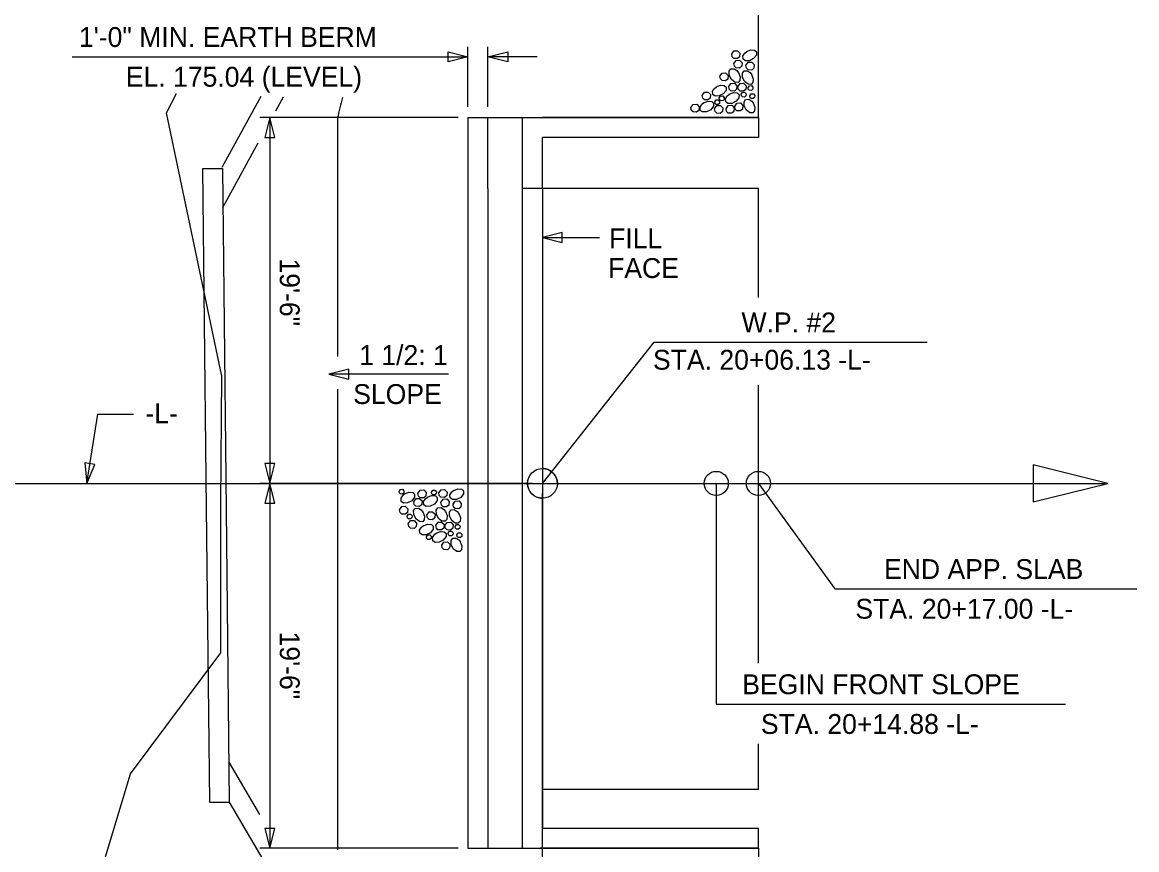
# Model space of a CAD drawing. Extents: x 471 to 2034, y -623 to 126.
# Drawn here: x 1602 to 1658.1, y -51.7 to -10 of the extents above; entities that cross this region are included whole.
import ezdxf

# ---------------------------------------------------------------- set-up
doc = ezdxf.new("R2010")
doc.units = 0
for name, color, linetype in [('Arrowhead Terminators CELL', 7, 'Continuous'), ('Auto Dimensioning', 7, 'Continuous'), ('Default', 7, 'Continuous'), ('Dimension Lines', 7, 'Continuous'), ('Exist Hydro Stream or Body of Water', 7, 'Continuous'), ('Exist Structure Major Bridge Seam', 7, 'Continuous'), ('Mis -L- Lines', 7, 'Continuous'), ('Mis Object Lines', 7, 'Continuous'), ('Mis Object Lines Hidden', 7, 'Continuous'), ('Mis Work Point CELL', 7, 'Continuous'), ('Miscellaneous Lines CELL', 7, 'Continuous'), ('Sub End Bent Cap Lines CELL', 7, 'Continuous'), ('Sup Concrete Girder Lines', 7, 'Continuous'), ('Text', 7, 'Continuous'), ('User Information Notes', 7, 'Continuous')]:
    doc.layers.add(name, color=color, linetype=linetype)

# ---------------------------------------------------------------- blocks, each defined once
blk = doc.blocks.new('AH')
at = {"layer": 'Sub End Bent Cap Lines CELL'}
blk.add_lwpolyline([(0, 0), (-1.25, 0.312), (-1.25, -0.312)], close=True, dxfattribs=at)

msp = doc.modelspace()

# ---------------------------------------------------------------- linework, layer by layer
at = {"layer": 'Arrowhead Terminators CELL'}
for points in [[(1628.207, -20.833), (1629.207, -21.083), (1629.207, -20.583)], [(1617.459, -27.719), (1618.459, -27.969), (1618.459, -27.469)], [(1605.264, -33.216), (1605.67, -32.268), (1605.176, -32.189)], [(1656.665, -33.216), (1652.915, -32.279), (1652.915, -34.154)]]:
    msp.add_lwpolyline(points, close=True, dxfattribs=at)
at = {"layer": 'Auto Dimensioning'}
for p, q in [((1623.957, -14.799), (1613.986, -14.799)), ((1614.486, -14.799), (1614.486, -33.216)), ((1627.707, -33.216), (1613.986, -33.216)), ((1614.486, -33.216), (1614.486, -51.588)), ((1628.189, -33.716), (1628.189, -65.55)), ((1623.957, -51.588), (1613.986, -51.588))]:
    msp.add_line(p, q, dxfattribs=at)
at = {"layer": 'Default'}
msp.add_line((1628.097, -51.588), (1638.097, -51.588), dxfattribs=at)
at = {"layer": 'Dimension Lines'}
for p, q in [((1604.538, -11.74), (1624.457, -11.74)), ((1624.457, -14.26), (1624.457, -11.24)), ((1625.457, -14.26), (1625.457, -11.24)), ((1627.938, -11.74), (1625.457, -11.74)), ((1628.207, -20.833), (1631.085, -20.833)), ((1628.207, -33.216), (1633.837, -26.111)), ((1633.837, -26.111), (1647.57, -26.111)), ((1623.481, -27.719), (1617.459, -27.719)), ((1605.264, -33.216), (1605.824, -29.735)), ((1605.824, -29.735), (1607.626, -29.735)), ((1636.957, -33.216), (1636.957, -44.333)), ((1639.077, -33.216), (1642.921, -38.531)), ((1642.921, -38.531), (1658.123, -38.531)), ((1636.957, -44.333), (1654.53, -44.333))]:
    msp.add_line(p, q, dxfattribs=at)
for centre in [(1636.957, -33.216), (1639.077, -33.216)]:
    msp.add_circle(centre, 0.606, dxfattribs=at)
at = {"layer": 'Exist Hydro Stream or Body of Water'}
for points in [[(1609.289, -14.552), (1609.784, -13.589)], [(1607.464, -47.845), (1612.022, -41.753), (1612.015, -34.19), (1612.069, -27.811), (1609.289, -14.552)], [(1607.95, -58.766), (1606.211, -52.027), (1607.464, -47.845)]]:
    msp.add_lwpolyline(points, dxfattribs=at)
at = {"layer": 'Exist Structure Major Bridge Seam'}
for p, q in [((1612.085, -17.293), (1614.049, -13.712)), ((1614.782, -14.457), (1615.172, -13.745)), ((1612.114, -19.32), (1613.899, -16.067)), ((1611.093, -17.359), (1612.093, -17.359)), ((1612.413, -47.257), (1613.959, -49.887)), ((1611.441, -49.277), (1612.441, -49.277)), ((1612.441, -49.277), (1617.662, -58.16))]:
    msp.add_line(p, q, dxfattribs=at)
for points in [[(1611.093, -17.359), (1611.263, -32.933), (1611.441, -49.277)], [(1612.093, -17.359), (1612.263, -32.933), (1612.441, -49.277)]]:
    msp.add_lwpolyline(points, dxfattribs=at)
at = {"layer": 'Mis -L- Lines'}
msp.add_line((1529.284, -33.216), (1656.541, -33.216), dxfattribs=at)
at = {"layer": 'Mis Object Lines'}
for p, q in [((1624.457, -14.799), (1639.077, -14.799)), ((1624.457, -14.799), (1624.457, -51.588)), ((1625.457, -18.362), (1625.457, -14.799)), ((1627.207, -51.588), (1627.207, -14.799)), ((1639.077, -14.799), (1639.077, -15.799)), ((1639.077, -15.799), (1628.207, -15.799)), ((1628.207, -18.362), (1628.207, -15.799)), ((1625.457, -18.362), (1625.457, -51.588)), ((1639.077, -18.362), (1627.207, -18.362)), ((1639.077, -23.863), (1639.077, -18.362)), ((1639.077, -42.275), (1639.077, -28.274)), ((1639.077, -48.633), (1639.077, -46.33)), ((1639.077, -48.633), (1628.207, -48.633)), ((1628.207, -48.633), (1628.207, -50.588)), ((1639.077, -50.588), (1628.207, -50.588)), ((1639.077, -51.588), (1639.077, -50.588)), ((1624.457, -51.588), (1639.077, -51.588))]:
    msp.add_line(p, q, dxfattribs=at)
at = {"layer": 'Mis Object Lines Hidden'}
msp.add_line((1628.207, -18.362), (1628.207, -49.196), dxfattribs=at)
at = {"layer": 'Mis Work Point CELL'}
for p, q in [((1628.207, -32.466), (1628.207, -33.216)), ((1627.457, -33.216), (1628.207, -33.216)), ((1628.207, -33.216), (1628.207, -33.966)), ((1628.207, -33.216), (1628.957, -33.216)), ((1628.957, -33.216), (1628.957, -33.216)), ((1628.207, -33.966), (1628.207, -33.966))]:
    msp.add_line(p, q, dxfattribs=at)
msp.add_circle((1628.207, -33.216), 0.75, dxfattribs=at)
for start, end in [(359.997, 89.9989), (180.0011, 270.003)]:
    msp.add_arc((1628.207, -33.216), 0.75, start, end, dxfattribs=at)
at = {"layer": 'Miscellaneous Lines CELL'}
for points in [[(1637.735, -11.596), (1637.847, -11.437), (1638.026, -11.427), (1638.15, -11.556), (1638.132, -11.736), (1638.022, -11.828), (1637.845, -11.816), (1637.762, -11.735), (1637.735, -11.596)], [(1638.487, -11.469), (1638.696, -11.386), (1638.889, -11.403), (1638.981, -11.49), (1638.978, -11.646), (1638.839, -11.823), (1638.624, -11.931), (1638.422, -11.934), (1638.308, -11.853), (1638.297, -11.692), (1638.39, -11.548), (1638.495, -11.464)], [(1638.074, -12.528), (1638.157, -12.737), (1638.14, -12.93), (1638.053, -13.021), (1637.897, -13.018), (1637.719, -12.88), (1637.612, -12.665), (1637.608, -12.463), (1637.689, -12.349), (1637.85, -12.338), (1637.995, -12.43), (1638.079, -12.536)], [(1637.84, -12.074), (1637.952, -11.914), (1638.131, -11.904), (1638.256, -12.033), (1638.238, -12.214), (1638.127, -12.306), (1637.951, -12.293), (1637.867, -12.212), (1637.841, -12.074)], [(1638.453, -12.171), (1638.565, -12.012), (1638.744, -12.002), (1638.868, -12.131), (1638.85, -12.311), (1638.74, -12.403), (1638.563, -12.39), (1638.48, -12.31), (1638.453, -12.171)], [(1637.136, -12.713), (1637.248, -12.554), (1637.427, -12.544), (1637.551, -12.673), (1637.533, -12.853), (1637.423, -12.945), (1637.246, -12.933), (1637.163, -12.852), (1637.136, -12.713)], [(1638.738, -12.629), (1638.821, -12.839), (1638.804, -13.031), (1638.717, -13.123), (1638.561, -13.12), (1638.384, -12.981), (1638.276, -12.767), (1638.273, -12.564), (1638.354, -12.45), (1638.515, -12.44), (1638.659, -12.532), (1638.743, -12.638)], [(1636.959, -13.248), (1637.169, -13.164), (1637.362, -13.181), (1637.453, -13.268), (1637.45, -13.424), (1637.311, -13.602), (1637.097, -13.709), (1636.894, -13.713), (1636.781, -13.632), (1636.77, -13.471), (1636.862, -13.327), (1636.968, -13.242)], [(1637.584, -13.233), (1637.697, -13.074), (1637.875, -13.063), (1638, -13.192), (1637.982, -13.373), (1637.871, -13.465), (1637.695, -13.452), (1637.612, -13.372), (1637.585, -13.233)], [(1638.045, -13.24), (1638.157, -13.08), (1638.336, -13.07), (1638.461, -13.199), (1638.443, -13.38), (1638.332, -13.472), (1638.156, -13.459), (1638.072, -13.378), (1638.046, -13.24)], [(1638.555, -13.289), (1638.622, -13.193), (1638.73, -13.187), (1638.804, -13.265), (1638.794, -13.373), (1638.727, -13.428), (1638.621, -13.42), (1638.571, -13.372), (1638.555, -13.289)], [(1636.329, -14.049), (1636.538, -13.966), (1636.731, -13.982), (1636.823, -14.07), (1636.82, -14.226), (1636.681, -14.403), (1636.466, -14.511), (1636.264, -14.514), (1636.15, -14.433), (1636.139, -14.272), (1636.231, -14.128), (1636.337, -14.044)], [(1636.251, -13.678), (1636.363, -13.519), (1636.541, -13.509), (1636.666, -13.638), (1636.648, -13.818), (1636.537, -13.91), (1636.361, -13.898), (1636.278, -13.817), (1636.251, -13.678)], [(1636.879, -14.004), (1636.946, -13.908), (1637.054, -13.902), (1637.128, -13.979), (1637.118, -14.088), (1637.051, -14.143), (1636.945, -14.135), (1636.895, -14.087), (1636.879, -14.004)], [(1637.11, -13.809), (1637.178, -13.713), (1637.285, -13.707), (1637.36, -13.785), (1637.349, -13.893), (1637.282, -13.948), (1637.176, -13.941), (1637.127, -13.892), (1637.11, -13.809)], [(1637.61, -13.622), (1637.819, -13.539), (1638.012, -13.556), (1638.103, -13.643), (1638.101, -13.799), (1637.962, -13.976), (1637.747, -14.084), (1637.545, -14.087), (1637.431, -14.006), (1637.42, -13.845), (1637.512, -13.701), (1637.618, -13.617)], [(1638.208, -13.625), (1638.276, -13.53), (1638.383, -13.523), (1638.458, -13.601), (1638.447, -13.709), (1638.381, -13.764), (1638.275, -13.757), (1638.225, -13.708), (1638.209, -13.625)], [(1638.819, -14.06), (1638.902, -14.269), (1638.886, -14.462), (1638.799, -14.553), (1638.642, -14.55), (1638.465, -14.411), (1638.357, -14.197), (1638.354, -13.995), (1638.435, -13.881), (1638.596, -13.87), (1638.74, -13.962), (1638.825, -14.068)], [(1638.65, -13.704), (1638.717, -13.608), (1638.824, -13.602), (1638.899, -13.68), (1638.888, -13.788), (1638.822, -13.843), (1638.716, -13.836), (1638.666, -13.787), (1638.65, -13.704)], [(1635.683, -14.295), (1635.795, -14.135), (1635.974, -14.125), (1636.098, -14.254), (1636.08, -14.435), (1635.969, -14.527), (1635.793, -14.514), (1635.71, -14.433), (1635.683, -14.295)], [(1636.872, -14.354), (1636.984, -14.194), (1637.163, -14.184), (1637.287, -14.313), (1637.269, -14.494), (1637.158, -14.586), (1636.982, -14.573), (1636.899, -14.492), (1636.872, -14.354)], [(1637.45, -14.347), (1637.562, -14.188), (1637.741, -14.178), (1637.865, -14.307), (1637.847, -14.487), (1637.737, -14.579), (1637.56, -14.566), (1637.477, -14.486), (1637.45, -14.347)], [(1637.884, -14.23), (1637.996, -14.071), (1638.175, -14.061), (1638.3, -14.19), (1638.282, -14.37), (1638.171, -14.462), (1637.994, -14.449), (1637.911, -14.369), (1637.884, -14.23)], [(1620.987, -33.617), (1621.054, -33.521), (1621.162, -33.515), (1621.236, -33.592), (1621.225, -33.701), (1621.159, -33.756), (1621.053, -33.748), (1621.003, -33.7), (1620.987, -33.617)], [(1621.277, -33.74), (1621.487, -33.656), (1621.68, -33.673), (1621.771, -33.76), (1621.768, -33.916), (1621.629, -34.094), (1621.415, -34.201), (1621.212, -34.205), (1621.098, -34.124), (1621.088, -33.963), (1621.18, -33.819), (1621.286, -33.734)], [(1621.941, -33.719), (1622.053, -33.56), (1622.232, -33.549), (1622.357, -33.678), (1622.339, -33.859), (1622.228, -33.951), (1622.051, -33.938), (1621.968, -33.858), (1621.941, -33.719)], [(1622.621, -33.654), (1622.688, -33.558), (1622.796, -33.552), (1622.87, -33.629), (1622.859, -33.738), (1622.793, -33.793), (1622.687, -33.785), (1622.637, -33.737), (1622.621, -33.654)], [(1622.988, -33.695), (1623.1, -33.536), (1623.279, -33.525), (1623.404, -33.654), (1623.386, -33.835), (1623.275, -33.927), (1623.098, -33.914), (1623.015, -33.833), (1622.988, -33.695)], [(1623.74, -33.567), (1623.95, -33.484), (1624.142, -33.501), (1624.234, -33.588), (1624.231, -33.744), (1624.092, -33.922), (1623.877, -34.029), (1623.675, -34.033), (1623.561, -33.952), (1623.55, -33.791), (1623.643, -33.646), (1623.749, -33.562)], [(1621.73, -34.141), (1621.842, -33.981), (1622.021, -33.971), (1622.146, -34.1), (1622.128, -34.281), (1622.017, -34.373), (1621.841, -34.36), (1621.757, -34.279), (1621.73, -34.141)], [(1622.416, -33.909), (1622.626, -33.826), (1622.818, -33.843), (1622.91, -33.93), (1622.907, -34.086), (1622.768, -34.263), (1622.553, -34.371), (1622.351, -34.374), (1622.237, -34.293), (1622.226, -34.132), (1622.319, -33.988), (1622.425, -33.904)], [(1623.094, -34.172), (1623.206, -34.013), (1623.385, -34.002), (1623.509, -34.131), (1623.491, -34.312), (1623.38, -34.404), (1623.204, -34.391), (1623.121, -34.311), (1623.094, -34.172)], [(1623.706, -34.27), (1623.818, -34.11), (1623.997, -34.1), (1624.122, -34.229), (1624.104, -34.41), (1623.993, -34.502), (1623.816, -34.489), (1623.733, -34.408), (1623.706, -34.27)], [(1621.012, -34.541), (1621.124, -34.381), (1621.303, -34.371), (1621.427, -34.5), (1621.409, -34.681), (1621.299, -34.773), (1621.122, -34.76), (1621.039, -34.679), (1621.012, -34.541)], [(1621.397, -34.867), (1621.464, -34.772), (1621.571, -34.766), (1621.646, -34.843), (1621.635, -34.951), (1621.569, -35.006), (1621.463, -34.999), (1621.413, -34.95), (1621.397, -34.867)], [(1622.188, -34.653), (1622.271, -34.863), (1622.255, -35.055), (1622.168, -35.147), (1622.011, -35.144), (1621.834, -35.005), (1621.726, -34.79), (1621.723, -34.588), (1621.804, -34.474), (1621.965, -34.464), (1622.109, -34.556), (1622.193, -34.662)], [(1622.389, -34.812), (1622.501, -34.652), (1622.68, -34.642), (1622.805, -34.771), (1622.787, -34.952), (1622.676, -35.044), (1622.5, -35.031), (1622.416, -34.95), (1622.389, -34.812)], [(1623.327, -34.626), (1623.41, -34.836), (1623.393, -35.028), (1623.306, -35.12), (1623.15, -35.117), (1622.973, -34.978), (1622.865, -34.763), (1622.862, -34.561), (1622.943, -34.447), (1623.104, -34.436), (1623.248, -34.529), (1623.332, -34.635)], [(1623.991, -34.728), (1624.074, -34.937), (1624.058, -35.13), (1623.971, -35.221), (1623.814, -35.219), (1623.637, -35.08), (1623.53, -34.865), (1623.526, -34.663), (1623.607, -34.549), (1623.768, -34.538), (1623.912, -34.63), (1623.997, -34.736)], [(1621.454, -35.252), (1621.566, -35.093), (1621.745, -35.083), (1621.869, -35.212), (1621.851, -35.392), (1621.741, -35.484), (1621.564, -35.472), (1621.481, -35.391), (1621.454, -35.252)], [(1622.213, -35.346), (1622.422, -35.263), (1622.615, -35.28), (1622.706, -35.367), (1622.704, -35.523), (1622.565, -35.7), (1622.35, -35.808), (1622.148, -35.811), (1622.034, -35.73), (1622.023, -35.569), (1622.115, -35.425), (1622.221, -35.341)], [(1622.838, -35.331), (1622.95, -35.172), (1623.129, -35.162), (1623.253, -35.291), (1623.235, -35.471), (1623.125, -35.563), (1622.948, -35.551), (1622.865, -35.47), (1622.838, -35.331)], [(1623.299, -35.338), (1623.411, -35.179), (1623.59, -35.169), (1623.714, -35.298), (1623.696, -35.478), (1623.586, -35.57), (1623.409, -35.557), (1623.326, -35.477), (1623.299, -35.338)], [(1623.809, -35.387), (1623.876, -35.292), (1623.983, -35.286), (1624.058, -35.363), (1624.047, -35.471), (1623.981, -35.527), (1623.875, -35.519), (1623.825, -35.471), (1623.809, -35.387)], [(1622.364, -35.908), (1622.431, -35.812), (1622.538, -35.806), (1622.613, -35.883), (1622.602, -35.992), (1622.536, -36.047), (1622.43, -36.039), (1622.38, -35.991), (1622.364, -35.908)], [(1622.863, -35.72), (1623.073, -35.637), (1623.265, -35.654), (1623.357, -35.741), (1623.354, -35.897), (1623.215, -36.075), (1623, -36.182), (1622.798, -36.186), (1622.684, -36.105), (1622.673, -35.944), (1622.766, -35.799), (1622.872, -35.715)], [(1623.462, -35.724), (1623.529, -35.628), (1623.636, -35.622), (1623.711, -35.699), (1623.7, -35.808), (1623.634, -35.863), (1623.528, -35.855), (1623.478, -35.807), (1623.462, -35.724)], [(1623.903, -35.802), (1623.97, -35.707), (1624.078, -35.701), (1624.152, -35.778), (1624.141, -35.886), (1624.075, -35.942), (1623.969, -35.934), (1623.919, -35.886), (1623.903, -35.803)], [(1623.138, -36.329), (1623.25, -36.169), (1623.429, -36.159), (1623.553, -36.288), (1623.535, -36.469), (1623.424, -36.561), (1623.248, -36.548), (1623.165, -36.467), (1623.138, -36.329)], [(1624.072, -36.158), (1624.156, -36.368), (1624.139, -36.56), (1624.052, -36.652), (1623.896, -36.649), (1623.718, -36.51), (1623.611, -36.295), (1623.607, -36.093), (1623.688, -35.979), (1623.849, -35.968), (1623.993, -36.061), (1624.078, -36.167)]]:
    msp.add_lwpolyline(points, dxfattribs=at)
at = {"layer": 'Sup Concrete Girder Lines'}
for p, q in [((1639.077, -14.824), (1639.077, 1.002)), ((1617.889, -14.831), (1617.889, -26.825)), ((1639.077, -14.799), (1628.207, -14.799)), ((1617.889, -28.475), (1617.889, -51.664)), ((1639.097, -51.588), (1628.097, -51.588)), ((1639.077, -51.588), (1639.077, -72.216))]:
    msp.add_line(p, q, dxfattribs=at)
msp.add_arc((1637.282, -18.801), 19.795, 165.3232, 168.4317, dxfattribs=at)
at = {"layer": 'User Information Notes'}
msp.add_line((1628.207, -33.216), (1628.207, -33.216), dxfattribs=at)
msp.add_line((1628.207, -33.216), (1628.207, -33.216), dxfattribs=at)

# ---------------------------------------------------------------- block references
at = {"layer": 'Arrowhead Terminators CELL', "xscale": 0.8, "yscale": -0.8000000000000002}
msp.add_blockref('AH', (1624.457, -11.74), dxfattribs=at)
at = {"layer": 'Arrowhead Terminators CELL', "xscale": 0.8, "yscale": -0.8000000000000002, "rotation": 180}
msp.add_blockref('AH', (1625.457, -11.74), dxfattribs=at)
at = {"layer": 'Auto Dimensioning', "xscale": 0.8, "yscale": 0.8000000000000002}
for p, rotation in [((1614.486, -14.799), 90), ((1614.486, -33.216), -90), ((1614.486, -33.216), 90), ((1614.486, -51.588), -90)]:
    msp.add_blockref('AH', p, dxfattribs=dict(at, rotation=rotation))

# ---------------------------------------------------------------- texts
at = {"layer": 'Dimension Lines'}
for s, p in [('FILL', (1631.561, -21.374)), ('FACE', (1631.51, -22.874)), ('-L-', (1608.22, -30.188))]:
    msp.add_text(s, height=1, dxfattribs=at).set_placement(p)
at = {"layer": 'Text'}
for s, p in [('1\'-0" MIN. EARTH BERM', (1604.873, -11.24)), ('EL. 175.04 (LEVEL)', (1607.232, -13.24)), ('W.P. #2', (1638.227, -25.611)), ('1 1/2: 1', (1618.98, -27.255)), ('STA. 20+06.13 -L-', (1633.77, -27.491)), ('SLOPE', (1618.679, -29.219)), ('END APP. SLAB', (1645.402, -38.031)), ('STA. 20+17.00 -L-', (1643.961, -40.031)), ('BEGIN FRONT SLOPE', (1638.265, -43.833)), ('STA. 20+14.88 -L-', (1639.204, -45.833))]:
    msp.add_text(s, height=1, dxfattribs=at).set_placement(p)
for p in [(1614.986, -21.89), (1614.986, -40.678)]:
    msp.add_text('19\'-6"', height=1, rotation=270, dxfattribs=at).set_placement(p)

doc.saveas('drawing.dxf')
